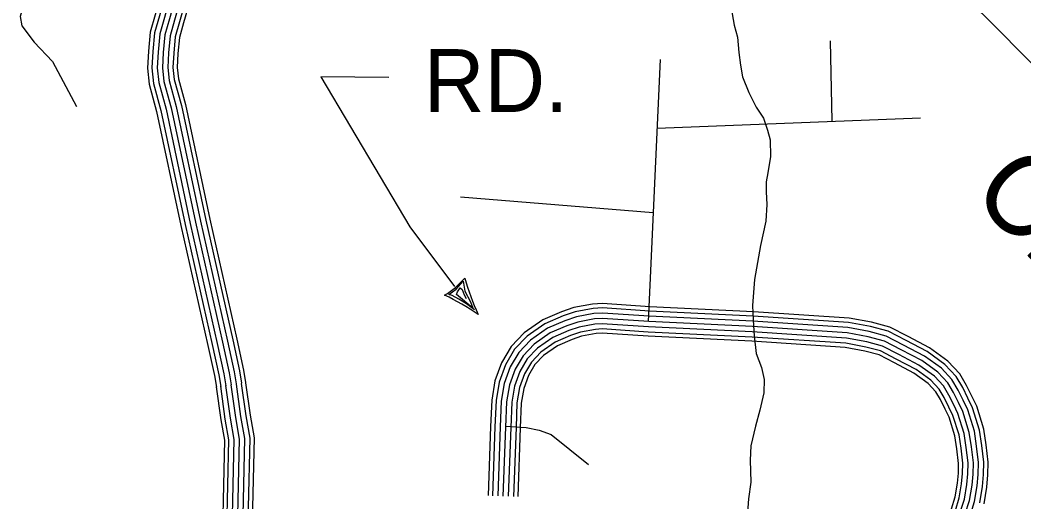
# Model space of a CAD drawing. Extents: x 1788175 to 1969470, y 584502 to 738744.
# Drawn here: x 1822589 to 1828504, y 694101 to 696941 of the extents above; entities that cross this region are included whole.
import ezdxf

# ---------------------------------------------------------------- set-up
doc = ezdxf.new("R2010")
doc.units = 0
for name, color, linetype in [('DESIGN - DRAINAGE - Bridges and Cross Drains Size Text', 7, 'Continuous'), ('DESIGN - ROW - Right-of-Way and Easement Labels', 7, 'Continuous'), ('DESIGN - TRANSPORTATION - Text', 7, 'Continuous'), ('SURVEY - CONTOURS - Index with Text', 7, 'Continuous'), ('SURVEY - TRANSPORTATION - Roads', 7, 'Continuous')]:
    doc.layers.add(name, color=color, linetype=linetype)

msp = doc.modelspace()

# ---------------------------------------------------------------- linework, layer by layer
at = {"layer": 'DESIGN - ROW - Right-of-Way and Easement Labels'}
for p, q in [((1825158.3, 695354.4), (1825199.7, 695402)), ((1825199.7, 695402), (1825209.9, 695342.6)), ((1825115.9, 695324), (1825158.3, 695354.4)), ((1825135.6, 695317.2), (1825115.9, 695324)), ((1825175.2, 695296.6), (1825135.6, 695317.2)), ((1825160.9, 695323.4), (1825166.7, 695339.4)), ((1825257.2, 695242.5), (1825160.9, 695323.4)), ((1825166.7, 695339.4), (1825182.2, 695362.2)), ((1825182.2, 695362.2), (1825193.4, 695352.2)), ((1825193.4, 695352.2), (1825206.6, 695321.8)), ((1825206.6, 695321.8), (1825217.6, 695299.1)), ((1825209.9, 695342.6), (1825243.1, 695280.5)), ((1825219.6, 695268.9), (1825175.2, 695296.6)), ((1825266.2, 695233.5), (1825219.6, 695268.9)), ((1825243.1, 695280.5), (1825257.2, 695242.5))]:
    msp.add_line(p, q, dxfattribs=at)
for points in [[(1824761.1, 696601.8), (1824361, 696605.8), (1824885.4, 695722.1)], [(1824885.4, 695722.1), (1825148.4, 695370.4)]]:
    msp.add_lwpolyline(points, dxfattribs=at)
for centre, radius, start, end in [((1824809.9, 695771.9), 532.3, 301.84446, 318.70286), ((1826545.4, 695792.3), 1386.4, 195.55293, 204.99147), ((1824422.3, 693918.8), 1552.3, 56.06124, 64.48901)]:
    msp.add_arc(centre, radius, start, end, dxfattribs=at)
at = {"layer": 'DESIGN - TRANSPORTATION - Text'}
for points in [[(1822594.8, 698074.7), (1822595.4, 697996.6), (1822624.2, 697928), (1822666.3, 697821.1), (1822680.6, 697726.7), (1822659.3, 697649), (1822650.6, 697607.1), (1822653.8, 697565), (1822692.4, 697488.2), (1822703.1, 697411.9), (1822677.9, 697340.3), (1822662.9, 697282.5), (1822630.8, 697160.9), (1822608.4, 697025.1), (1822589.3, 696961.4), (1822600.4, 696907.1), (1822672.6, 696809.7), (1822780.5, 696697.6), (1822921.7, 696430.8)], [(1827572.5, 697684.5), (1827632.4, 697627.9), (1827725.9, 697569.2), (1827793.3, 697504.6), (1827832.9, 697454.3), (1827896.7, 697429.8), (1827952.3, 697393.4), (1828002, 697361), (1828049.5, 697292.6), (1828085.1, 697244.3), (1828134.7, 697199.9), (1828168.3, 697149.7), (1828191.8, 697089.4), (1828219.3, 697017.2), (1828292.7, 696944.6), (1828552.5, 696682.5)], [(1826755.8, 697146.7), (1826797, 696910.2), (1826815.7, 696839.8), (1826824.1, 696749.6), (1826834.8, 696675.3), (1826845.5, 696607), (1826883.8, 696514.3), (1826926.3, 696427.4), (1826969.1, 696362.6), (1826993.8, 696292.1), (1827008.8, 696235.8), (1827011, 696137.6), (1826995.3, 696039.8), (1826984.4, 695987.9), (1826985.3, 695927.8), (1826990, 695853.7), (1826982.3, 695755.7), (1826951.7, 695612.1), (1826916.2, 695412.5), (1826905.5, 695258.5), (1826908, 695172.4), (1826914.3, 695080.2), (1826926.5, 694975.8), (1826957, 694893.2), (1826973.7, 694822.8), (1826972.3, 694744.8), (1826948.5, 694641.1), (1826922.9, 694547.4), (1826894.8, 694431.8), (1826891.3, 694347.8), (1826895, 694217.6), (1826881.3, 694119.7), (1826873.4, 694013.7)]]:
    msp.add_lwpolyline(points, dxfattribs=at)
at = {"layer": 'SURVEY - CONTOURS - Index with Text'}
for points in [[(1823675.2, 698041.6), (1823678.3, 697977.7), (1823673.7, 697898.3), (1823651.2, 697748), (1823613.9, 697616.6), (1823519.8, 697354.8), (1823425, 697100.6), (1823409.3, 697059.3), (1823385.2, 696971.8), (1823355.9, 696870.5), (1823345.7, 696756.6), (1823340.1, 696658.2), (1823350, 696562.2), (1823394, 696402.4), (1823536.8, 695730.3), (1823695.9, 695023.4), (1823735, 694845.3), (1823746.2, 694777)], [(1823700.9, 698042.9), (1823704.1, 697977.6), (1823699.4, 697895.7), (1823676.4, 697742.5), (1823638.4, 697608.7), (1823544, 697346), (1823449.1, 697091.5), (1823433.8, 697051.3), (1823410, 696964.8), (1823381.3, 696865.7), (1823371.4, 696754.7), (1823365.9, 696658.8), (1823375.3, 696567), (1823419, 696408.5), (1823561.9, 695735.8), (1823721, 695029), (1823760.3, 694850.1), (1823771.6, 694781.1)], [(1823731.9, 698044.4), (1823735.1, 697977.4), (1823730.2, 697892.5), (1823706.8, 697736), (1823667.9, 697599.3), (1823573.1, 697335.3), (1823478.1, 697080.6), (1823463.3, 697041.6), (1823439.8, 696956.4), (1823411.9, 696859.9), (1823402.3, 696752.5), (1823397, 696659.5), (1823405.9, 696572.7), (1823449.1, 696415.9), (1823592.2, 695742.4), (1823751.2, 695035.7), (1823790.7, 694856), (1823802.2, 694786.2)], [(1823762.8, 698045.9), (1823766.2, 697977.3), (1823761.1, 697889.3), (1823737.1, 697729.4), (1823697.4, 697589.8), (1823602.2, 697324.7), (1823507.1, 697069.6), (1823492.8, 697032), (1823469.6, 696948), (1823442.5, 696854.2), (1823433.2, 696750.2), (1823428.1, 696660.2), (1823436.5, 696578.5), (1823479.2, 696423.2), (1823622.5, 695749), (1823781.5, 695042.5), (1823821.2, 694861.8), (1823832.8, 694791.2)], [(1823762.8, 698045.9), (1823766.2, 697977.3), (1823761.1, 697889.3), (1823737.1, 697729.4), (1823697.4, 697589.8), (1823602.2, 697324.7), (1823507.1, 697069.6), (1823492.8, 697032), (1823469.6, 696948), (1823442.5, 696854.2), (1823433.2, 696750.2), (1823428.1, 696660.2), (1823436.5, 696578.5), (1823479.2, 696423.2), (1823622.5, 695749), (1823781.5, 695042.5), (1823821.2, 694861.8), (1823832.8, 694791.2)], [(1823793.8, 698047.4), (1823797.2, 697977.1), (1823792, 697886.1), (1823767.5, 697722.8), (1823726.9, 697580.3), (1823631.3, 697314), (1823536.1, 697058.7), (1823522.2, 697022.3), (1823499.5, 696939.5), (1823473.1, 696848.5), (1823464.1, 696748), (1823459.2, 696660.9), (1823467.1, 696584.2), (1823509.4, 696430.5), (1823652.8, 695755.7), (1823811.7, 695049.2), (1823851.6, 694867.7), (1823863.4, 694796.2)], [(1823824.8, 698048.9), (1823828.3, 697977), (1823822.8, 697882.9), (1823797.8, 697716.3), (1823756.5, 697570.8), (1823660.4, 697303.4), (1823565.1, 697047.7), (1823551.7, 697012.7), (1823529.3, 696931.1), (1823503.7, 696842.7), (1823495, 696745.7), (1823490.3, 696661.6), (1823497.6, 696590), (1823539.5, 696437.9), (1823683.1, 695762.3), (1823842, 695055.9), (1823882.1, 694873.5), (1823894, 694801.2)], [(1823849.4, 698050.1), (1823853, 697976.9), (1823847.4, 697880.3), (1823822, 697711), (1823780, 697563.2), (1823683.6, 697294.9), (1823588.3, 697039), (1823575.3, 697005), (1823553.1, 696924.4), (1823528.1, 696838.1), (1823519.7, 696743.9), (1823515, 696662.2), (1823522, 696594.5), (1823563.5, 696443.7), (1823707.2, 695767.6), (1823866.1, 695061.3), (1823906.4, 694878.2), (1823918.4, 694805.2)], [(1823635.4, 691694.1), (1823656, 691930.2), (1823759, 692749.6), (1823833.2, 693663.8), (1823850.9, 694469.7), (1823829.2, 694594.3), (1823802.1, 694786.9)], [(1823666.3, 691691.4), (1823686.9, 691927), (1823789.8, 692746.4), (1823864.1, 693662.2), (1823882, 694472), (1823859.9, 694599.1), (1823832.8, 694791.2)], [(1823666.3, 691691.4), (1823686.9, 691927), (1823789.8, 692746.4), (1823864.1, 693662.2), (1823882, 694472), (1823859.9, 694599.1), (1823832.8, 694791.2)], [(1823697.2, 691688.7), (1823717.7, 691923.7), (1823820.6, 692743.2), (1823895.1, 693660.6), (1823913, 694474.3), (1823890.5, 694604), (1823863.5, 694795.5)], [(1823728.1, 691686), (1823748.5, 691920.4), (1823851.5, 692740), (1823926.1, 693659.1), (1823944.1, 694476.7), (1823921.1, 694608.8), (1823894.2, 694799.8)], [(1823753.7, 691683.8), (1823774.1, 691917.7), (1823877.1, 692737.4), (1823951.8, 693657.7), (1823969.9, 694478.6), (1823946.5, 694612.8), (1823919.6, 694803.4)], [(1823579.9, 691698.9), (1823600.6, 691936.1), (1823703.5, 692755.3), (1823777.5, 693666.7), (1823795.1, 694465.5), (1823774.2, 694585.7), (1823746.9, 694779.1)], [(1823604.5, 691696.8), (1823625.2, 691933.5), (1823728.1, 692752.8), (1823802.2, 693665.4), (1823819.9, 694467.3), (1823798.6, 694589.5), (1823771.4, 694782.5)]]:
    msp.add_lwpolyline(points, dxfattribs=at)
at = {"layer": 'SURVEY - TRANSPORTATION - Roads'}
for points in [[(1827373.4, 696344.9), (1827363.7, 696818.2)], [(1826360.6, 696709), (1826320.4, 695806.3), (1826290, 695164.3)], [(1826342.6, 696304.5), (1827893.7, 696365.3)], [(1825184.4, 695898.3), (1826320.4, 695806.5)], [(1828268.7, 694090.1), (1828285.3, 694188.8), (1828291.9, 694260.5), (1828293.8, 694336.3), (1828281.6, 694437.9), (1828268, 694530.3), (1828225.6, 694665.4), (1828197.1, 694724.7), (1828166.5, 694787.7), (1828125.4, 694856.4), (1828055.1, 694931.2), (1827948.2, 695009.1), (1827821.2, 695075.7), (1827713.1, 695131.5), (1827605.3, 695159.9), (1827473.4, 695185), (1826910.3, 695222.2), (1826299.4, 695251.7), (1826020.6, 695270.5), (1825962.2, 695267.3), (1825852.6, 695246.2), (1825779.2, 695222), (1825668.9, 695173.9), (1825560, 695097), (1825482.3, 695016.4), (1825426, 694920.9), (1825387.4, 694814.3), (1825367.9, 694701.1), (1825361.8, 694545.1), (1825346.7, 694138.9)], [(1828243.6, 694096.1), (1828259.8, 694192.1), (1828266.2, 694262), (1828268, 694335.1), (1828256.1, 694434.5), (1828242.8, 694524.5), (1828201.6, 694656), (1828174, 694713.5), (1828143.8, 694775.4), (1828104.8, 694840.8), (1828038, 694911.9), (1827934.6, 694987.2), (1827809.3, 695052.9), (1827703.8, 695107.4), (1827599.6, 695134.8), (1827470.2, 695159.5), (1826908.9, 695196.5), (1826297.9, 695226), (1826020.4, 695244.7), (1825965.3, 695241.7), (1825859.1, 695221.3), (1825788.4, 695197.9), (1825681.6, 695151.4), (1825576.8, 695077.4), (1825502.9, 695000.7), (1825449.3, 694909.9), (1825412.4, 694807.7), (1825393.5, 694698.4), (1825387.5, 694544.1), (1825372.4, 694137.9)], [(1828187.4, 694019.9), (1828213.4, 694103.4), (1828229.1, 694196.1), (1828235.2, 694263.8), (1828237, 694333.6), (1828225.4, 694430.4), (1828212.5, 694517.5), (1828172.7, 694644.6), (1828146.1, 694700), (1828116.5, 694760.7), (1828079.9, 694822), (1828017.4, 694888.5), (1827918.2, 694960.8), (1827795, 695025.4), (1827692.6, 695078.3), (1827592.7, 695104.6), (1827466.2, 695128.7), (1826907.1, 695165.6), (1826296.1, 695195), (1826020.2, 695213.7), (1825969.1, 695210.8), (1825866.9, 695191.2), (1825799.5, 695168.9), (1825696.8, 695124.3), (1825597.1, 695053.8), (1825527.8, 694981.8), (1825477.5, 694896.7), (1825442.5, 694799.7), (1825424.4, 694695.1), (1825418.5, 694543), (1825403.4, 694136.8)], [(1828158.2, 694030.5), (1828183.2, 694110.6), (1828198.3, 694200.1), (1828204.2, 694265.6), (1828205.9, 694332.1), (1828194.7, 694426.3), (1828182.2, 694510.6), (1828143.8, 694633.2), (1828118.1, 694686.5), (1828089.2, 694745.9), (1828055, 694803.3), (1827996.8, 694865.2), (1827901.8, 694934.4), (1827780.7, 694997.9), (1827681.5, 695049.2), (1827585.9, 695074.3), (1827462.3, 695097.9), (1826905.3, 695134.6), (1826294.4, 695164.1), (1826020, 695182.6), (1825972.9, 695180), (1825874.8, 695161.2), (1825810.6, 695139.9), (1825712.1, 695097.1), (1825617.4, 695030.2), (1825552.6, 694962.9), (1825505.7, 694883.4), (1825472.6, 694791.7), (1825455.3, 694691.9), (1825449.5, 694541.8), (1825434.4, 694135.6)], [(1828158.2, 694030.5), (1828183.2, 694110.6), (1828198.3, 694200.1), (1828204.2, 694265.6), (1828205.9, 694332.1), (1828194.7, 694426.3), (1828182.2, 694510.6), (1828143.8, 694633.2), (1828118.1, 694686.5), (1828089.2, 694745.9), (1828055, 694803.3), (1827996.8, 694865.2), (1827901.8, 694934.4), (1827780.7, 694997.9), (1827681.5, 695049.2), (1827585.9, 695074.3), (1827462.3, 695097.9), (1826905.3, 695134.6), (1826294.4, 695164.1), (1826020, 695182.6), (1825972.9, 695180), (1825874.8, 695161.2), (1825810.6, 695139.9), (1825712.1, 695097.1), (1825617.4, 695030.2), (1825552.6, 694962.9), (1825505.7, 694883.4), (1825472.6, 694791.7), (1825455.3, 694691.9), (1825449.5, 694541.8), (1825434.4, 694135.6)], [(1828129, 694041), (1828153, 694117.8), (1828167.5, 694204.1), (1828173.3, 694267.4), (1828174.9, 694330.7), (1828163.9, 694422.2), (1828151.9, 694503.6), (1828114.8, 694621.8), (1828090.2, 694673), (1828061.9, 694731.2), (1828030.1, 694784.5), (1827976.2, 694841.8), (1827885.4, 694908), (1827766.4, 694970.4), (1827670.3, 695020), (1827579, 695044.1), (1827458.4, 695067), (1826903.6, 695103.7), (1826292.6, 695133.1), (1826019.8, 695151.5), (1825976.7, 695149.2), (1825882.6, 695131.1), (1825821.6, 695110.9), (1825727.4, 695069.9), (1825637.7, 695006.6), (1825577.5, 694944), (1825533.8, 694870.2), (1825502.7, 694783.8), (1825486.2, 694688.6), (1825480.4, 694540.6), (1825465.4, 694134.5)], [(1828099.9, 694051.6), (1828122.8, 694125), (1828136.8, 694208.1), (1828142.3, 694269.2), (1828143.8, 694329.2), (1828133.2, 694418.1), (1828121.6, 694496.7), (1828085.9, 694610.4), (1828062.3, 694659.6), (1828034.6, 694716.4), (1828005.2, 694765.7), (1827955.6, 694818.5), (1827869, 694881.6), (1827752.1, 694942.9), (1827659.1, 694990.9), (1827572.2, 695013.8), (1827454.4, 695036.2), (1826901.8, 695072.7), (1826290.8, 695102.2), (1826019.6, 695120.5), (1825980.5, 695118.3), (1825890.4, 695101), (1825832.7, 695082), (1825742.7, 695042.8), (1825658, 694982.9), (1825602.3, 694925.1), (1825562, 694856.9), (1825532.7, 694775.8), (1825517.1, 694685.3), (1825511.4, 694539.4), (1825496.4, 694133.3)], [(1828076.6, 694060), (1828098.7, 694130.8), (1828112.2, 694211.3), (1828117.6, 694270.6), (1828119.1, 694328.1), (1828108.7, 694414.8), (1828097.4, 694491.2), (1828062.9, 694601.3), (1828040.1, 694648.8), (1828012.9, 694704.6), (1827985.4, 694750.7), (1827939.2, 694799.9), (1827855.9, 694860.5), (1827740.7, 694921), (1827650.1, 694967.7), (1827566.7, 694989.7), (1827451.3, 695011.7), (1826900.4, 695048.1), (1826289.3, 695077.5), (1826019.5, 695095.7), (1825983.5, 695093.7), (1825896.6, 695077.1), (1825841.5, 695058.9), (1825754.9, 695021.1), (1825674.2, 694964.1), (1825622.1, 694910.1), (1825584.5, 694846.3), (1825556.7, 694769.5), (1825541.8, 694682.7), (1825536.1, 694538.5), (1825521.1, 694132.4)], [(1825449.7, 694547.6), (1825571.3, 694540.3), (1825647, 694523.4), (1825718.6, 694498.5), (1825938.2, 694321.7)]]:
    msp.add_lwpolyline(points, dxfattribs=at)

# ---------------------------------------------------------------- texts
at = {"layer": 'DESIGN - DRAINAGE - Bridges and Cross Drains Size Text'}
msp.add_text('Cr.', height=475, rotation=313.19051, dxfattribs=at).set_placement((1828179.4, 695919.7))
at = {"layer": 'DESIGN - ROW - Right-of-Way and Easement Labels'}
msp.add_text('RD.', height=370, dxfattribs=at).set_placement((1824968.2, 696399.4))

doc.saveas('drawing.dxf')
